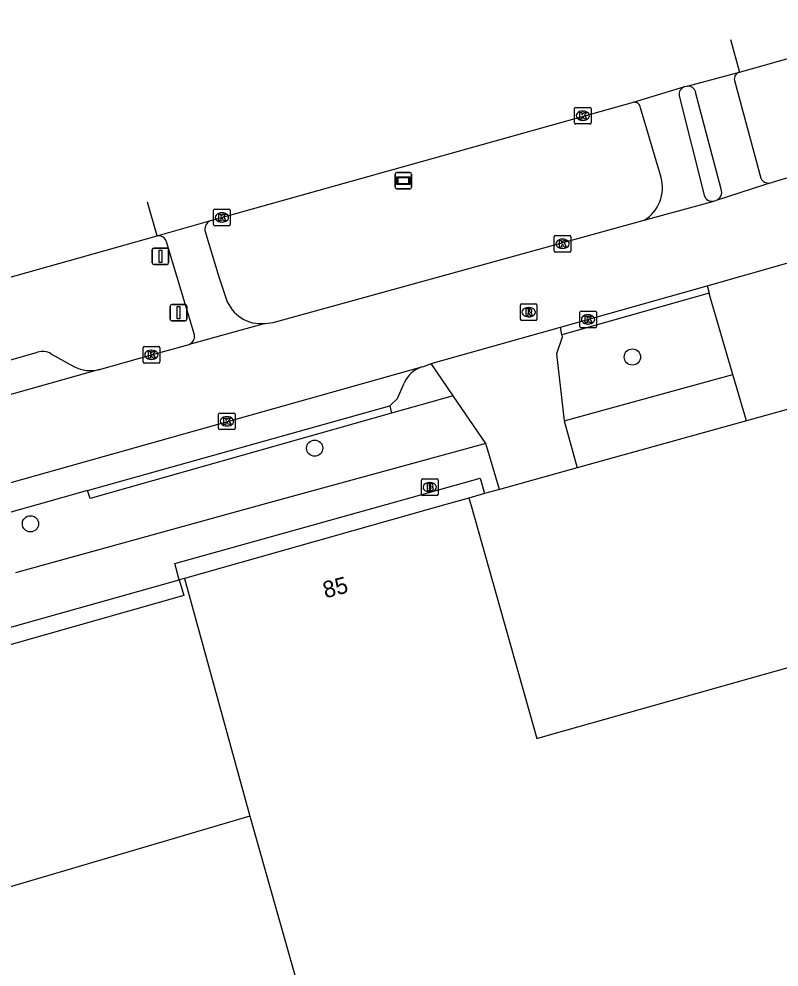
# Model space of a CAD drawing. Extents: x 159689 to 160786, y 387323 to 388339.
# Drawn here: x 160014.4 to 160060.1, y 388222.2 to 388279.2 of the extents above; entities that cross this region are included whole.
import ezdxf

# ---------------------------------------------------------------- set-up
doc = ezdxf.new("R2010")
doc.units = 0
for name, color, linetype in [('IMGEO_Afsluitpaal', 7, 'Continuous'), ('IMGEO_Boom', 7, 'Continuous'), ('IMGEO_Brandkraan', 7, 'Continuous'), ('IMGEO_Fietspad_open', 7, 'Continuous'), ('IMGEO_Kolk', 7, 'Continuous'), ('IMGEO_Pand', 7, 'Continuous'), ('IMGEO_Pand_nummerreeks', 7, 'Continuous'), ('IMGEO_Parkeervlak_open', 7, 'Continuous'), ('IMGEO_Rijbaan_lokaal_open', 7, 'Continuous'), ('IMGEO_Rijbaan_regionaal_gesloten', 7, 'Continuous'), ('IMGEO_Rioolput', 7, 'Continuous'), ('IMGEO_Straatnaambord', 7, 'Continuous'), ('IMGEO_Verkeersbordpaal', 7, 'Continuous'), ('IMGEO_Voetpad_open', 7, 'Continuous')]:
    doc.layers.add(name, color=color, linetype=linetype)

msp = doc.modelspace()

# ---------------------------------------------------------------- linework, layer by layer
at = {"layer": 'IMGEO_Afsluitpaal'}
for p, q in [((160023.486, 388261.141), (160023.486, 388261.941)), ((160023.486, 388261.941), (160023.486, 388261.141)), ((160023.586, 388262.041), (160024.376, 388262.041)), ((160024.376, 388262.041), (160023.586, 388262.041)), ((160024.476, 388261.941), (160024.476, 388261.141)), ((160024.476, 388261.141), (160024.476, 388261.941)), ((160024.376, 388261.041), (160023.586, 388261.041)), ((160023.586, 388261.041), (160024.376, 388261.041))]:
    msp.add_line(p, q, dxfattribs=at)
msp.add_lwpolyline([(160023.906, 388261.916), (160024.056, 388261.916), (160024.056, 388261.166), (160023.906, 388261.166), (160023.906, 388261.916)], dxfattribs=at)
for centre, start, end in [((160023.586, 388261.941), 90, 180), ((160023.586, 388261.941), 90, 180), ((160024.376, 388261.941), 0, 90), ((160024.376, 388261.941), 360, 90), ((160023.586, 388261.141), 180, 270), ((160023.586, 388261.141), 180, 270), ((160024.376, 388261.141), 270, 0), ((160024.376, 388261.141), 270, 0)]:
    msp.add_arc(centre, 0.1, start, end, dxfattribs=at)
at = {"layer": 'IMGEO_Boom'}
for centre in [(160051.283, 388258.873), (160032.174, 388253.39), (160015.082, 388248.84)]:
    msp.add_circle(centre, 0.489, dxfattribs=at)
at = {"layer": 'IMGEO_Brandkraan'}
for p, q in [((160038.596, 388250.617), (160038.596, 388251.469)), ((160038.671, 388251.543), (160039.523, 388251.543)), ((160039.597, 388251.469), (160039.597, 388250.617)), ((160039.084, 388251.323), (160039.109, 388251.323)), ((160039.523, 388250.543), (160038.671, 388250.543)), ((160039.107, 388250.763), (160039.082, 388250.763))]:
    msp.add_line(p, q, dxfattribs=at)
for points in [[(160038.596, 388250.617), (160038.596, 388251.469)], [(160038.671, 388251.543), (160039.523, 388251.543)], [(160039.597, 388251.469), (160039.597, 388250.617)], [(160038.944, 388251.243), (160038.944, 388250.843), (160039.157, 388250.843)], [(160039.175, 388251.243), (160038.944, 388251.243)], [(160039.123, 388251.162), (160039.069, 388251.162), (160039.069, 388251.086)], [(160039.069, 388251.086), (160039.122, 388251.086)], [(160039.131, 388251.01), (160039.069, 388251.01), (160039.069, 388250.929)], [(160039.069, 388250.929), (160039.131, 388250.929)], [(160039.523, 388250.543), (160038.671, 388250.543)]]:
    msp.add_lwpolyline(points, dxfattribs=at)
for centre, radius, start, end in [((160038.673, 388251.467), 0.0765, 91.552, 178.448), ((160038.673, 388251.467), 0.0765, 91.552, 178.448), ((160039.521, 388251.467), 0.0765, 1.552, 88.448), ((160039.521, 388251.467), 0.0765, 1.552, 88.448), ((160039.124, 388251.124), 0.0379, 267.8285, 90.9355), ((160039.132, 388250.969), 0.0404, 269.8759, 90.5077), ((160039.163, 388251.094), 0.251, 268.6676, 293.5347), ((160039.179, 388251.098), 0.145, 59.4692, 91.5367), ((160039.204, 388251.145), 0.0922, 285.5137, 58.1501), ((160039.209, 388250.953), 0.105, 301.3115, 78.989), ((160038.673, 388250.619), 0.0765, 181.552, 268.448), ((160038.673, 388250.619), 0.0765, 181.552, 268.448), ((160039.521, 388250.619), 0.0765, 271.552, 358.448), ((160039.521, 388250.619), 0.0765, 271.552, 358.448)]:
    msp.add_arc(centre, radius, start, end, dxfattribs=at)
for centre, major_axis, ratio, start_param, end_param in [((160039.083, 388251.043), (-0.387, 0.002), 0.722429, 4.712389, 7.853982), ((160039.108, 388251.043), (-0.39, 0.002), 0.717154, 1.570796, 4.712389)]:
    msp.add_ellipse(centre, major_axis=major_axis, ratio=ratio, start_param=start_param, end_param=end_param, dxfattribs=at)
at = {"layer": 'IMGEO_Fietspad_open'}
for points in [[(160054.097, 388274.579), (160055.606, 388268.603)], [(160053.014, 388269.665), (160051.769, 388273.87)], [(160025.572, 388266.477), (160026.41, 388263.689), (160026.85, 388262.379)], [(160024.941, 388260.211), (160023.887, 388263.747), (160023.269, 388265.805)]]:
    msp.add_lwpolyline(points, dxfattribs=at)
for centre, radius, start, end in [((160054.582, 388274.67), 0.493, 107.9293, 190.5956), ((160051.403, 388273.835), 0.367, 5.3943, 99.1557), ((160050.793, 388269.064), 2.301, 301.5783, 15.1433), ((160056.067, 388268.716), 0.475, 193.8117, 281.513), ((160026.141, 388266.551), 0.574, 111.04, 187.3651), ((160022.79, 388265.672), 0.497, 15.4851, 99.3345), ((160028.936, 388263.083), 2.201, 198.6626, 276.8981), ((160024.395, 388260.13), 0.552, 295.7528, 8.4526)]:
    msp.add_arc(centre, radius, start, end, dxfattribs=at)
at = {"layer": 'IMGEO_Kolk'}
for p, q in [((160047.803, 388272.966), (160047.803, 388273.818)), ((160047.878, 388273.892), (160048.73, 388273.892)), ((160048.291, 388273.672), (160048.316, 388273.672)), ((160048.804, 388273.818), (160048.804, 388272.966)), ((160048.314, 388273.112), (160048.289, 388273.112)), ((160048.73, 388272.892), (160047.878, 388272.892)), ((160026.093, 388266.848), (160026.093, 388267.7)), ((160026.168, 388267.774), (160027.02, 388267.774)), ((160026.581, 388267.554), (160026.606, 388267.554)), ((160027.094, 388267.7), (160027.094, 388266.848)), ((160026.604, 388266.994), (160026.579, 388266.994)), ((160027.02, 388266.774), (160026.168, 388266.774)), ((160046.581, 388265.258), (160046.581, 388266.11)), ((160046.656, 388266.184), (160047.508, 388266.184)), ((160047.069, 388265.964), (160047.094, 388265.964)), ((160047.582, 388266.11), (160047.582, 388265.258)), ((160047.508, 388265.184), (160046.656, 388265.184)), ((160047.092, 388265.404), (160047.067, 388265.404)), ((160048.118, 388260.713), (160048.118, 388261.565)), ((160048.193, 388261.639), (160049.045, 388261.639)), ((160048.606, 388261.419), (160048.631, 388261.419)), ((160049.119, 388261.565), (160049.119, 388260.713)), ((160049.045, 388260.639), (160048.193, 388260.639)), ((160048.629, 388260.859), (160048.604, 388260.859)), ((160021.854, 388258.579), (160021.854, 388259.431)), ((160021.929, 388259.505), (160022.781, 388259.505)), ((160022.855, 388259.431), (160022.855, 388258.579)), ((160022.342, 388259.285), (160022.367, 388259.285)), ((160022.781, 388258.505), (160021.929, 388258.505)), ((160022.365, 388258.725), (160022.34, 388258.725)), ((160026.397, 388254.578), (160026.397, 388255.43)), ((160026.472, 388255.504), (160027.324, 388255.504)), ((160027.398, 388255.43), (160027.398, 388254.578)), ((160026.885, 388255.284), (160026.91, 388255.284)), ((160027.324, 388254.504), (160026.472, 388254.504)), ((160026.908, 388254.724), (160026.883, 388254.724))]:
    msp.add_line(p, q, dxfattribs=at)
for points in [[(160047.803, 388272.966), (160047.803, 388273.818)], [(160047.878, 388273.892), (160048.73, 388273.892)], [(160048.804, 388273.818), (160048.804, 388272.966)], [(160048.124, 388273.592), (160048.247, 388273.592), (160048.247, 388273.441), (160048.377, 388273.592), (160048.541, 388273.592), (160048.395, 388273.441), (160048.548, 388273.192), (160048.396, 388273.192), (160048.311, 388273.356), (160048.247, 388273.289), (160048.247, 388273.192), (160048.124, 388273.192), (160048.124, 388273.592)], [(160048.73, 388272.892), (160047.878, 388272.892)], [(160026.093, 388266.848), (160026.093, 388267.7)], [(160026.168, 388267.774), (160027.02, 388267.774)], [(160026.414, 388267.474), (160026.537, 388267.474), (160026.537, 388267.323), (160026.667, 388267.474), (160026.831, 388267.474), (160026.685, 388267.323), (160026.838, 388267.074), (160026.686, 388267.074), (160026.601, 388267.238), (160026.537, 388267.171), (160026.537, 388267.074), (160026.414, 388267.074), (160026.414, 388267.474)], [(160027.094, 388267.7), (160027.094, 388266.848)], [(160027.02, 388266.774), (160026.168, 388266.774)], [(160046.581, 388265.258), (160046.581, 388266.11)], [(160046.656, 388266.184), (160047.508, 388266.184)], [(160046.902, 388265.884), (160047.025, 388265.884), (160047.025, 388265.733), (160047.155, 388265.884), (160047.319, 388265.884), (160047.173, 388265.733), (160047.326, 388265.484), (160047.174, 388265.484), (160047.089, 388265.648), (160047.025, 388265.581), (160047.025, 388265.484), (160046.902, 388265.484), (160046.902, 388265.884)], [(160047.582, 388266.11), (160047.582, 388265.258)], [(160047.508, 388265.184), (160046.656, 388265.184)], [(160048.118, 388260.713), (160048.118, 388261.565)], [(160048.193, 388261.639), (160049.045, 388261.639)], [(160048.439, 388261.339), (160048.562, 388261.339), (160048.562, 388261.188), (160048.692, 388261.339), (160048.856, 388261.339), (160048.71, 388261.188), (160048.863, 388260.939), (160048.711, 388260.939), (160048.626, 388261.103), (160048.562, 388261.036), (160048.562, 388260.939), (160048.439, 388260.939), (160048.439, 388261.339)], [(160049.119, 388261.565), (160049.119, 388260.713)], [(160049.045, 388260.639), (160048.193, 388260.639)], [(160021.854, 388258.579), (160021.854, 388259.431)], [(160021.929, 388259.505), (160022.781, 388259.505)], [(160022.855, 388259.431), (160022.855, 388258.579)], [(160022.175, 388259.205), (160022.298, 388259.205), (160022.298, 388259.054), (160022.428, 388259.205), (160022.592, 388259.205), (160022.446, 388259.054), (160022.599, 388258.805), (160022.447, 388258.805), (160022.362, 388258.969), (160022.298, 388258.902), (160022.298, 388258.805), (160022.175, 388258.805), (160022.175, 388259.205)], [(160022.781, 388258.505), (160021.929, 388258.505)], [(160026.397, 388254.578), (160026.397, 388255.43)], [(160026.472, 388255.504), (160027.324, 388255.504)], [(160027.398, 388255.43), (160027.398, 388254.578)], [(160026.718, 388255.204), (160026.841, 388255.204), (160026.841, 388255.053), (160026.971, 388255.204), (160027.135, 388255.204), (160026.989, 388255.053), (160027.142, 388254.804), (160026.99, 388254.804), (160026.905, 388254.968), (160026.841, 388254.901), (160026.841, 388254.804), (160026.718, 388254.804), (160026.718, 388255.204)], [(160027.324, 388254.504), (160026.472, 388254.504)]]:
    msp.add_lwpolyline(points, dxfattribs=at)
for centre, start, end in [((160047.88, 388273.816), 91.552, 178.448), ((160047.88, 388273.816), 91.552, 178.448), ((160048.728, 388273.816), 1.552, 88.448), ((160048.728, 388273.816), 1.552, 88.448), ((160047.88, 388272.968), 181.552, 268.448), ((160047.88, 388272.968), 181.552, 268.448), ((160048.728, 388272.968), 271.552, 358.448), ((160048.728, 388272.968), 271.552, 358.448), ((160026.17, 388267.698), 91.552, 178.448), ((160026.17, 388267.698), 91.552, 178.448), ((160027.018, 388267.698), 1.552, 88.448), ((160027.018, 388267.698), 1.552, 88.448), ((160026.17, 388266.85), 181.552, 268.448), ((160026.17, 388266.85), 181.552, 268.448), ((160027.018, 388266.85), 271.552, 358.448), ((160027.018, 388266.85), 271.552, 358.448), ((160046.658, 388266.108), 91.552, 178.448), ((160046.658, 388266.108), 91.552, 178.448), ((160047.506, 388266.108), 1.552, 88.448), ((160047.506, 388266.108), 1.552, 88.448), ((160046.658, 388265.26), 181.552, 268.448), ((160046.658, 388265.26), 181.552, 268.448), ((160047.506, 388265.26), 271.552, 358.448), ((160047.506, 388265.26), 271.552, 358.448), ((160048.195, 388261.563), 91.552, 178.448), ((160048.195, 388261.563), 91.552, 178.448), ((160049.043, 388261.563), 1.552, 88.448), ((160049.043, 388261.563), 1.552, 88.448), ((160048.195, 388260.715), 181.552, 268.448), ((160048.195, 388260.715), 181.552, 268.448), ((160049.043, 388260.715), 271.552, 358.448), ((160049.043, 388260.715), 271.552, 358.448), ((160021.931, 388259.429), 91.552, 178.448), ((160021.931, 388259.429), 91.552, 178.448), ((160022.779, 388259.429), 1.552, 88.448), ((160022.779, 388259.429), 1.552, 88.448), ((160021.931, 388258.581), 181.552, 268.448), ((160021.931, 388258.581), 181.552, 268.448), ((160022.779, 388258.581), 271.552, 358.448), ((160022.779, 388258.581), 271.552, 358.448), ((160026.474, 388255.428), 91.552, 178.448), ((160026.474, 388255.428), 91.552, 178.448), ((160027.322, 388255.428), 1.552, 88.448), ((160027.322, 388255.428), 1.552, 88.448), ((160026.474, 388254.58), 181.552, 268.448), ((160026.474, 388254.58), 181.552, 268.448), ((160027.322, 388254.58), 271.552, 358.448), ((160027.322, 388254.58), 271.552, 358.448)]:
    msp.add_arc(centre, 0.0765, start, end, dxfattribs=at)
for centre, major_axis, ratio, start_param, end_param in [((160048.29, 388273.392), (-0.387, 0.002), 0.722429, 4.712389, 7.853982), ((160048.315, 388273.392), (-0.39, 0.002), 0.717154, 1.570796, 4.712389), ((160026.58, 388267.274), (-0.387, 0.002), 0.722429, 4.712389, 7.853982), ((160026.605, 388267.274), (-0.39, 0.002), 0.717154, 1.570796, 4.712389), ((160047.068, 388265.684), (-0.387, 0.002), 0.722429, 4.712389, 7.853982), ((160047.093, 388265.684), (-0.39, 0.002), 0.717154, 1.570796, 4.712389), ((160048.605, 388261.139), (-0.387, 0.002), 0.722429, 4.712389, 7.853982), ((160048.63, 388261.139), (-0.39, 0.002), 0.717154, 1.570796, 4.712389), ((160022.341, 388259.005), (-0.387, 0.002), 0.722429, 4.712389, 7.853982), ((160022.366, 388259.005), (-0.39, 0.002), 0.717154, 1.570796, 4.712389), ((160026.884, 388255.004), (-0.387, 0.002), 0.722429, 4.712389, 7.853982), ((160026.909, 388255.004), (-0.39, 0.002), 0.717154, 1.570796, 4.712389)]:
    msp.add_ellipse(centre, major_axis=major_axis, ratio=ratio, start_param=start_param, end_param=end_param, dxfattribs=at)
at = {"layer": 'IMGEO_Pand'}
for points in [[(160041.45, 388250.39), (160040.071, 388250), (160024.342, 388245.552)], [(160041.45, 388250.39), (160041.56, 388250), (160045.541, 388235.923), (160046.447, 388236.179), (160062.209, 388240.637), (160063.993, 388234.327)], [(160024.034, 388245.465), (160024.301, 388244.521), (160012.64, 388241.223)], [(160024.342, 388245.552), (160024.034, 388245.465)], [(160024.342, 388245.552), (160028.276, 388231.249)], [(160028.276, 388231.249), (160000.662, 388223.107)], [(160028.276, 388231.249), (160033.501, 388212.759), (160034.861, 388207.947), (160035.314, 388208.074)]]:
    msp.add_lwpolyline(points, dxfattribs=at)
at = {"layer": 'IMGEO_Parkeervlak_open'}
for points in [[(159998.67, 388252.937), (159999.361, 388254.039), (160000, 388254.644), (160000.615, 388254.949), (160007.575, 388256.899), (160015.513, 388259.16)], [(160016.315, 388259.071), (160017.695, 388258.296)], [(160018.518, 388250.844), (160015.536, 388250), (160012.6, 388249.169)]]:
    msp.add_lwpolyline(points, dxfattribs=at)
for centre, radius, start, end in [((160015.822, 388258.282), 0.93, 57.9649, 109.3704), ((160018.703, 388260.311), 2.253, 243.4177, 283.7062)]:
    msp.add_arc(centre, radius, start, end, dxfattribs=at)
at = {"layer": 'IMGEO_Rijbaan_lokaal_open'}
for points in [[(160059.559, 388269.345), (160059.684, 388269.382), (160059.703, 388269.388), (160065.679, 388271.181)], [(160056.336, 388268.307), (160056.409, 388268.33), (160059.184, 388269.232), (160059.559, 388269.345)], [(160051.998, 388267.104), (160056.034, 388268.216), (160056.162, 388268.251)], [(160056.162, 388268.251), (160056.189, 388268.259), (160056.249, 388268.278), (160056.336, 388268.307)], [(160029.2, 388260.898), (160029.685, 388260.955), (160051.998, 388267.104)], [(160055.779, 388263.153), (160060.574, 388264.522)], [(160046.952, 388260.666), (160055.779, 388263.153)], [(160029.2, 388260.898), (160024.635, 388259.633)], [(160039.171, 388258.474), (160046.952, 388260.666)], [(160019.237, 388258.122), (160022.355, 388259.004), (160024.635, 388259.633)], [(159858.217, 388207.473), (159948.035, 388232.803), (159952.178, 388233.968), (160000, 388247.417), (160009.184, 388250), (160038.617, 388258.278)], [(160038.617, 388258.278), (160038.735, 388258.311), (160039.171, 388258.474)], [(160019.237, 388258.122), (160000, 388252.717), (159997.692, 388252.069)]]:
    msp.add_lwpolyline(points, dxfattribs=at)
at = {"layer": 'IMGEO_Rijbaan_regionaal_gesloten'}
for points in [[(160057.725, 388276.015), (160069.085, 388279.211)], [(160057.181, 388277.973), (160057.725, 388276.015)], [(160054.571, 388275.176), (160057.725, 388276.015)], [(160051.345, 388274.198), (160054.43, 388275.139)], [(160054.43, 388275.139), (160054.571, 388275.176)], [(160025.935, 388267.086), (160051.345, 388274.198)], [(160022.709, 388266.163), (160022.114, 388268.189)], [(160022.709, 388266.163), (160025.935, 388267.086)], [(159919.6, 388237.172), (159948.924, 388245.417), (160022.709, 388266.163)]]:
    msp.add_lwpolyline(points, dxfattribs=at)
at = {"layer": 'IMGEO_Rioolput'}
for p, q in [((160044.543, 388261.145), (160044.543, 388261.997)), ((160044.618, 388262.071), (160045.47, 388262.071)), ((160045.031, 388261.851), (160045.056, 388261.851)), ((160045.544, 388261.997), (160045.544, 388261.145)), ((160045.054, 388261.291), (160045.029, 388261.291)), ((160045.47, 388261.071), (160044.618, 388261.071))]:
    msp.add_line(p, q, dxfattribs=at)
for points in [[(160044.543, 388261.145), (160044.543, 388261.997)], [(160044.618, 388262.071), (160045.47, 388262.071)], [(160045.132, 388261.769), (160044.88, 388261.771), (160044.88, 388261.371)], [(160045.058, 388261.69), (160045.004, 388261.69), (160045.004, 388261.609)], [(160045.544, 388261.997), (160045.544, 388261.145)], [(160044.88, 388261.371), (160045.004, 388261.371), (160045.004, 388261.533), (160045.015, 388261.533)], [(160045.004, 388261.609), (160045.056, 388261.609)], [(160045.062, 388261.504), (160045.133, 388261.371), (160045.273, 388261.371), (160045.208, 388261.497)], [(160045.47, 388261.071), (160044.618, 388261.071)]]:
    msp.add_lwpolyline(points, dxfattribs=at)
for centre, radius, start, end in [((160044.62, 388261.995), 0.0765, 91.552, 178.448), ((160044.62, 388261.995), 0.0765, 91.552, 178.448), ((160045.064, 388261.594), 0.0964, 77.0061, 93.1865), ((160045.078, 388261.651), 0.0378, 276.6634, 79.6772), ((160045.131, 388261.659), 0.109, 350.3612, 89.416), ((160045.468, 388261.995), 0.0765, 1.552, 88.448), ((160045.468, 388261.995), 0.0765, 1.552, 88.448), ((160044.62, 388261.147), 0.0765, 181.552, 268.448), ((160044.62, 388261.147), 0.0765, 181.552, 268.448), ((160045.014, 388261.48), 0.0533, 26.0293, 88.6989), ((160045.04, 388261.798), 0.19, 274.7715, 282.9687), ((160045.129, 388261.659), 0.112, 277.5842, 350.9817), ((160045.113, 388261.444), 0.108, 29.5134, 73.7905), ((160045.468, 388261.147), 0.0765, 271.552, 358.448), ((160045.468, 388261.147), 0.0765, 271.552, 358.448)]:
    msp.add_arc(centre, radius, start, end, dxfattribs=at)
for centre, major_axis, ratio, start_param, end_param in [((160045.03, 388261.571), (-0.387, 0.002), 0.722429, 4.712389, 7.853982), ((160045.055, 388261.571), (-0.39, 0.002), 0.717154, 1.570796, 4.712389)]:
    msp.add_ellipse(centre, major_axis=major_axis, ratio=ratio, start_param=start_param, end_param=end_param, dxfattribs=at)
at = {"layer": 'IMGEO_Straatnaambord'}
for p, q in [((160037.016, 388269.082), (160037.016, 388269.882)), ((160037.016, 388269.882), (160037.016, 388269.082)), ((160037.116, 388269.982), (160037.906, 388269.982)), ((160037.906, 388269.982), (160037.116, 388269.982)), ((160038.006, 388269.882), (160038.006, 388269.082)), ((160038.006, 388269.082), (160038.006, 388269.882)), ((160037.906, 388268.982), (160037.116, 388268.982)), ((160037.116, 388268.982), (160037.906, 388268.982))]:
    msp.add_line(p, q, dxfattribs=at)
for points in [[(160037.117, 388269.714), (160037.905, 388269.714), (160037.905, 388269.25), (160037.117, 388269.25), (160037.117, 388269.714)], [(160037.182, 388269.649), (160037.182, 388269.315), (160037.84, 388269.315), (160037.84, 388269.649), (160037.182, 388269.649)]]:
    msp.add_lwpolyline(points, dxfattribs=at)
for centre, start, end in [((160037.116, 388269.882), 90, 180), ((160037.116, 388269.882), 90, 180), ((160037.906, 388269.882), 0, 90), ((160037.906, 388269.882), 360, 90), ((160037.116, 388269.082), 180, 270), ((160037.116, 388269.082), 180, 270), ((160037.906, 388269.082), 270, 0), ((160037.906, 388269.082), 270, 0)]:
    msp.add_arc(centre, 0.1, start, end, dxfattribs=at)
at = {"layer": 'IMGEO_Verkeersbordpaal'}
for p, q in [((160022.403, 388264.532), (160022.403, 388265.332)), ((160022.403, 388265.332), (160022.403, 388264.532)), ((160022.503, 388265.432), (160023.293, 388265.432)), ((160023.293, 388265.432), (160022.503, 388265.432)), ((160023.393, 388265.332), (160023.393, 388264.532)), ((160023.393, 388264.532), (160023.393, 388265.332)), ((160023.293, 388264.432), (160022.503, 388264.432)), ((160022.503, 388264.432), (160023.293, 388264.432))]:
    msp.add_line(p, q, dxfattribs=at)
msp.add_lwpolyline([(160022.823, 388265.307), (160022.973, 388265.307), (160022.973, 388264.557), (160022.823, 388264.557), (160022.823, 388265.307)], dxfattribs=at)
for centre, start, end in [((160022.503, 388265.332), 90, 180), ((160022.503, 388265.332), 90, 180), ((160023.293, 388265.332), 0, 90), ((160023.293, 388265.332), 360, 90), ((160022.503, 388264.532), 180, 270), ((160022.503, 388264.532), 180, 270), ((160023.293, 388264.532), 270, 0), ((160023.293, 388264.532), 270, 0)]:
    msp.add_arc(centre, 0.1, start, end, dxfattribs=at)
at = {"layer": 'IMGEO_Voetpad_open'}
for points in [[(160057.414, 388275.503), (160059.005, 388269.627)], [(160056.622, 388268.979), (160055.087, 388274.809)], [(160055.779, 388263.153), (160055.897, 388262.719)], [(160055.897, 388262.719), (160047.03, 388260.213)], [(160057.323, 388257.819), (160055.982, 388262.405), (160055.897, 388262.719)], [(160047.03, 388260.213), (160046.952, 388260.666)], [(160047.03, 388260.213), (160047.054, 388260.076), (160046.723, 388259.058), (160047.18, 388255.041)], [(160040.499, 388256.54), (160039.171, 388258.474)], [(160047.18, 388255.041), (160057.323, 388257.819)], [(160058.138, 388255.033), (160057.323, 388257.819)], [(160036.686, 388255.944), (160037.159, 388256.385), (160037.564, 388257.303)], [(160040.499, 388256.54), (160036.794, 388255.492)], [(160042.467, 388253.676), (160040.499, 388256.54)], [(160062.828, 388256.338), (160058.138, 388255.033)], [(160018.518, 388250.844), (160036.686, 388255.944)], [(160036.794, 388255.492), (160018.67, 388250.364), (160018.518, 388250.844)], [(160036.686, 388255.944), (160036.794, 388255.492)], [(160047.18, 388255.041), (160047.957, 388252.2)], [(160058.138, 388255.033), (160047.957, 388252.2)], [(160042.467, 388253.676), (160029.06, 388250), (160014.187, 388245.896)], [(160043.294, 388250.903), (160042.467, 388253.676)], [(160047.957, 388252.2), (160043.294, 388250.903)], [(160024.034, 388245.465), (160023.766, 388246.446), (160036.465, 388250), (160042.135, 388251.587), (160042.396, 388250.653)], [(160043.294, 388250.903), (160042.396, 388250.653)], [(160042.396, 388250.653), (160041.45, 388250.39)], [(160012.369, 388242.192), (160024.034, 388245.465)]]:
    msp.add_lwpolyline(points, dxfattribs=at)
for centre, radius, start, end in [((160057.857, 388275.584), 0.451, 107.0638, 190.3854), ((160054.619, 388274.697), 0.482, 13.4961, 95.66), ((160059.477, 388269.869), 0.531, 207.165, 278.8806), ((160056.132, 388268.791), 0.525, 292.844, 21.0473), ((160039.135, 388256.662), 1.697, 107.7784, 157.8164)]:
    msp.add_arc(centre, radius, start, end, dxfattribs=at)

# ---------------------------------------------------------------- texts
at = {"layer": 'IMGEO_Pand_nummerreeks'}
msp.add_text('85', height=1, rotation=14.5073, dxfattribs=at).set_placement((160032.818, 388244.35))

doc.saveas('drawing.dxf')
